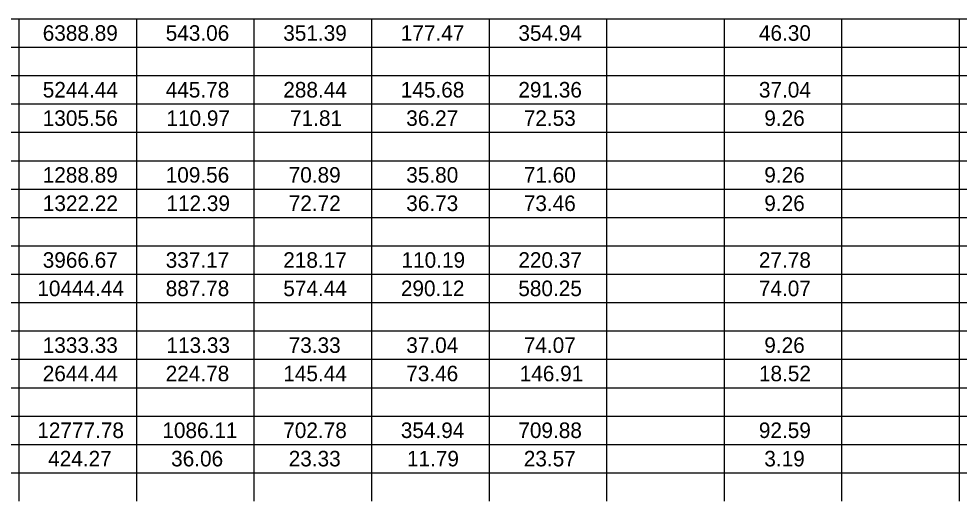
# Model space of a CAD drawing. Extents: x 0 to 34.4, y 0 to 47.
# Drawn here: x 16.38 to 25.65, y 5 to 9.75 of the extents above; entities that cross this region are included whole.
import ezdxf

# ---------------------------------------------------------------- set-up
doc = ezdxf.new("R2010")
doc.units = 0
doc.layers.add('SH_Text', color=7, linetype='Continuous')

msp = doc.modelspace()

# ---------------------------------------------------------------- linework, layer by layer
at = {"layer": 'SH_Text'}
for p, q in [((15.2196, 9.7518), (16.3784, 9.7518)), ((16.3784, 9.7518), (24.4903, 9.7518)), ((16.3784, 9.7518), (16.3784, 9.472)), ((17.5373, 9.7518), (17.5373, 9.472)), ((18.6961, 9.7518), (18.6961, 9.472)), ((19.855, 9.7518), (19.855, 9.472)), ((21.0138, 9.7518), (21.0138, 9.472)), ((22.1726, 9.7518), (22.1726, 9.472)), ((23.3315, 9.7518), (23.3315, 9.472)), ((24.4903, 9.7518), (25.6492, 9.7518)), ((24.4903, 9.7518), (24.4903, 9.472)), ((25.6492, 9.7518), (27.9668, 9.7518)), ((25.6492, 9.7518), (25.6492, 9.472)), ((15.2196, 9.472), (16.3784, 9.472)), ((16.3784, 9.472), (24.4903, 9.472)), ((16.3784, 9.472), (16.3784, 9.1923)), ((17.5373, 9.472), (17.5373, 9.1923)), ((18.6961, 9.472), (18.6961, 9.1923)), ((19.855, 9.472), (19.855, 9.1923)), ((21.0138, 9.472), (21.0138, 9.1923)), ((22.1726, 9.472), (22.1726, 9.1923)), ((23.3315, 9.472), (23.3315, 9.1923)), ((24.4903, 9.472), (25.6492, 9.472)), ((24.4903, 9.472), (24.4903, 9.1923)), ((25.6492, 9.472), (27.9668, 9.472)), ((25.6492, 9.472), (25.6492, 9.1923)), ((15.2196, 9.1923), (16.3784, 9.1923)), ((16.3784, 9.1923), (24.4903, 9.1923)), ((16.3784, 9.1923), (16.3784, 8.9126)), ((17.5373, 9.1923), (17.5373, 8.9126)), ((18.6961, 9.1923), (18.6961, 8.9126)), ((19.855, 9.1923), (19.855, 8.9126)), ((21.0138, 9.1923), (21.0138, 8.9126)), ((22.1726, 9.1923), (22.1726, 8.9126)), ((23.3315, 9.1923), (23.3315, 8.9126)), ((24.4903, 9.1923), (25.6492, 9.1923)), ((24.4903, 9.1923), (24.4903, 8.9126)), ((25.6492, 9.1923), (27.9668, 9.1923)), ((25.6492, 9.1923), (25.6492, 8.9126)), ((15.2196, 8.9126), (16.3784, 8.9126)), ((16.3784, 8.9126), (24.4903, 8.9126)), ((16.3784, 8.9126), (16.3784, 8.6329)), ((17.5373, 8.9126), (17.5373, 8.6329)), ((18.6961, 8.9126), (18.6961, 8.6329)), ((19.855, 8.9126), (19.855, 8.6329)), ((21.0138, 8.9126), (21.0138, 8.6329)), ((22.1726, 8.9126), (22.1726, 8.6329)), ((23.3315, 8.9126), (23.3315, 8.6329)), ((24.4903, 8.9126), (25.6492, 8.9126)), ((24.4903, 8.9126), (24.4903, 8.6329)), ((25.6492, 8.9126), (27.9668, 8.9126)), ((25.6492, 8.9126), (25.6492, 8.6329)), ((15.2196, 8.6329), (16.3784, 8.6329)), ((16.3784, 8.6329), (24.4903, 8.6329)), ((16.3784, 8.6329), (16.3784, 8.3532)), ((17.5373, 8.6329), (17.5373, 8.3532)), ((18.6961, 8.6329), (18.6961, 8.3532)), ((19.855, 8.6329), (19.855, 8.3532)), ((21.0138, 8.6329), (21.0138, 8.3532)), ((22.1726, 8.6329), (22.1726, 8.3532)), ((23.3315, 8.6329), (23.3315, 8.3532)), ((24.4903, 8.6329), (25.6492, 8.6329)), ((24.4903, 8.6329), (24.4903, 8.3532)), ((25.6492, 8.6329), (27.9668, 8.6329)), ((25.6492, 8.6329), (25.6492, 8.3532)), ((15.2196, 8.3532), (16.3784, 8.3532)), ((16.3784, 8.3532), (24.4903, 8.3532)), ((16.3784, 8.3532), (16.3784, 8.0734)), ((17.5373, 8.3532), (17.5373, 8.0734)), ((18.6961, 8.3532), (18.6961, 8.0734)), ((19.855, 8.3532), (19.855, 8.0734)), ((21.0138, 8.3532), (21.0138, 8.0734)), ((22.1726, 8.3532), (22.1726, 8.0734)), ((23.3315, 8.3532), (23.3315, 8.0734)), ((24.4903, 8.3532), (25.6492, 8.3532)), ((24.4903, 8.3532), (24.4903, 8.0734)), ((25.6492, 8.3532), (27.9668, 8.3532)), ((25.6492, 8.3532), (25.6492, 8.0734)), ((15.2196, 8.0734), (16.3784, 8.0734)), ((16.3784, 8.0734), (24.4903, 8.0734)), ((16.3784, 8.0734), (16.3784, 7.7937)), ((17.5373, 8.0734), (17.5373, 7.7937)), ((18.6961, 8.0734), (18.6961, 7.7937)), ((19.855, 8.0734), (19.855, 7.7937)), ((21.0138, 8.0734), (21.0138, 7.7937)), ((22.1726, 8.0734), (22.1726, 7.7937)), ((23.3315, 8.0734), (23.3315, 7.7937)), ((24.4903, 8.0734), (25.6492, 8.0734)), ((24.4903, 8.0734), (24.4903, 7.7937)), ((25.6492, 8.0734), (27.9668, 8.0734)), ((25.6492, 8.0734), (25.6492, 7.7937)), ((15.2196, 7.7937), (16.3784, 7.7937)), ((16.3784, 7.7937), (24.4903, 7.7937)), ((16.3784, 7.7937), (16.3784, 7.514)), ((17.5373, 7.7937), (17.5373, 7.514)), ((18.6961, 7.7937), (18.6961, 7.514)), ((19.855, 7.7937), (19.855, 7.514)), ((21.0138, 7.7937), (21.0138, 7.514)), ((22.1726, 7.7937), (22.1726, 7.514)), ((23.3315, 7.7937), (23.3315, 7.514)), ((24.4903, 7.7937), (25.6492, 7.7937)), ((24.4903, 7.7937), (24.4903, 7.514)), ((25.6492, 7.7937), (27.9668, 7.7937)), ((25.6492, 7.7937), (25.6492, 7.514)), ((15.2196, 7.514), (16.3784, 7.514)), ((16.3784, 7.514), (24.4903, 7.514)), ((16.3784, 7.514), (16.3784, 7.2343)), ((17.5373, 7.514), (17.5373, 7.2343)), ((18.6961, 7.514), (18.6961, 7.2343)), ((19.855, 7.514), (19.855, 7.2343)), ((21.0138, 7.514), (21.0138, 7.2343)), ((22.1726, 7.514), (22.1726, 7.2343)), ((23.3315, 7.514), (23.3315, 7.2343)), ((24.4903, 7.514), (25.6492, 7.514)), ((24.4903, 7.514), (24.4903, 7.2343)), ((25.6492, 7.514), (27.9668, 7.514)), ((25.6492, 7.514), (25.6492, 7.2343)), ((15.2196, 7.2343), (16.3784, 7.2343)), ((16.3784, 7.2343), (24.4903, 7.2343)), ((16.3784, 7.2343), (16.3784, 6.9546)), ((17.5373, 7.2343), (17.5373, 6.9546)), ((18.6961, 7.2343), (18.6961, 6.9546)), ((19.855, 7.2343), (19.855, 6.9546)), ((21.0138, 7.2343), (21.0138, 6.9546)), ((22.1726, 7.2343), (22.1726, 6.9546)), ((23.3315, 7.2343), (23.3315, 6.9546)), ((24.4903, 7.2343), (25.6492, 7.2343)), ((24.4903, 7.2343), (24.4903, 6.9546)), ((25.6492, 7.2343), (27.9668, 7.2343)), ((25.6492, 7.2343), (25.6492, 6.9546)), ((15.2196, 6.9546), (16.3784, 6.9546)), ((16.3784, 6.9546), (24.4903, 6.9546)), ((16.3784, 6.9546), (16.3784, 6.6748)), ((17.5373, 6.9546), (17.5373, 6.6748)), ((18.6961, 6.9546), (18.6961, 6.6748)), ((19.855, 6.9546), (19.855, 6.6748)), ((21.0138, 6.9546), (21.0138, 6.6748)), ((22.1726, 6.9546), (22.1726, 6.6748)), ((23.3315, 6.9546), (23.3315, 6.6748)), ((24.4903, 6.9546), (25.6492, 6.9546)), ((24.4903, 6.9546), (24.4903, 6.6748)), ((25.6492, 6.9546), (27.9668, 6.9546)), ((25.6492, 6.9546), (25.6492, 6.6748)), ((15.2196, 6.6748), (16.3784, 6.6748)), ((16.3784, 6.6748), (24.4903, 6.6748)), ((16.3784, 6.6748), (16.3784, 6.3951)), ((17.5373, 6.6748), (17.5373, 6.3951)), ((18.6961, 6.6748), (18.6961, 6.3951)), ((19.855, 6.6748), (19.855, 6.3951)), ((21.0138, 6.6748), (21.0138, 6.3951)), ((22.1726, 6.6748), (22.1726, 6.3951)), ((23.3315, 6.6748), (23.3315, 6.3951)), ((24.4903, 6.6748), (25.6492, 6.6748)), ((24.4903, 6.6748), (24.4903, 6.3951)), ((25.6492, 6.6748), (27.9668, 6.6748)), ((25.6492, 6.6748), (25.6492, 6.3951)), ((15.2196, 6.3951), (16.3784, 6.3951)), ((16.3784, 6.3951), (24.4903, 6.3951)), ((16.3784, 6.3951), (16.3784, 6.1154)), ((17.5373, 6.3951), (17.5373, 6.1154)), ((18.6961, 6.3951), (18.6961, 6.1154)), ((19.855, 6.3951), (19.855, 6.1154)), ((21.0138, 6.3951), (21.0138, 6.1154)), ((22.1726, 6.3951), (22.1726, 6.1154)), ((23.3315, 6.3951), (23.3315, 6.1154)), ((24.4903, 6.3951), (25.6492, 6.3951)), ((24.4903, 6.3951), (24.4903, 6.1154)), ((25.6492, 6.3951), (27.9668, 6.3951)), ((25.6492, 6.3951), (25.6492, 6.1154)), ((15.2196, 6.1154), (16.3784, 6.1154)), ((16.3784, 6.1154), (24.4903, 6.1154)), ((16.3784, 6.1154), (16.3784, 5.8357)), ((17.5373, 6.1154), (17.5373, 5.8357)), ((18.6961, 6.1154), (18.6961, 5.8357)), ((19.855, 6.1154), (19.855, 5.8357)), ((21.0138, 6.1154), (21.0138, 5.8357)), ((22.1726, 6.1154), (22.1726, 5.8357)), ((23.3315, 6.1154), (23.3315, 5.8357)), ((24.4903, 6.1154), (25.6492, 6.1154)), ((24.4903, 6.1154), (24.4903, 5.8357)), ((25.6492, 6.1154), (27.9668, 6.1154)), ((25.6492, 6.1154), (25.6492, 5.8357)), ((15.2196, 5.8357), (16.3784, 5.8357)), ((16.3784, 5.8357), (24.4903, 5.8357)), ((16.3784, 5.8357), (16.3784, 5.556)), ((17.5373, 5.8357), (17.5373, 5.556)), ((18.6961, 5.8357), (18.6961, 5.556)), ((19.855, 5.8357), (19.855, 5.556)), ((21.0138, 5.8357), (21.0138, 5.556)), ((22.1726, 5.8357), (22.1726, 5.556)), ((23.3315, 5.8357), (23.3315, 5.556)), ((24.4903, 5.8357), (25.6492, 5.8357)), ((24.4903, 5.8357), (24.4903, 5.556)), ((25.6492, 5.8357), (27.9668, 5.8357)), ((25.6492, 5.8357), (25.6492, 5.556)), ((15.2196, 5.556), (16.3784, 5.556)), ((16.3784, 5.556), (24.4903, 5.556)), ((16.3784, 5.556), (16.3784, 4.9965)), ((17.5373, 5.556), (17.5373, 4.9965)), ((18.6961, 5.556), (18.6961, 4.9965)), ((19.855, 5.556), (19.855, 4.9965)), ((21.0138, 5.556), (21.0138, 4.9965)), ((22.1726, 5.556), (22.1726, 4.9965)), ((23.3315, 5.556), (23.3315, 4.9965)), ((24.4903, 5.556), (25.6492, 5.556)), ((24.4903, 5.556), (24.4903, 4.9965)), ((25.6492, 5.556), (27.9668, 5.556)), ((25.6492, 5.556), (25.6492, 4.9965)), ((15.2196, 5.2762), (16.3784, 5.2762)), ((16.3784, 5.2762), (24.4903, 5.2762)), ((24.4903, 5.2762), (25.6492, 5.2762)), ((25.6492, 5.2762), (27.9668, 5.2762))]:
    msp.add_line(p, q, dxfattribs=at)

# ---------------------------------------------------------------- texts
for s, p in [('6388.89', (16.6142, 9.5353)), ('543.06', (17.8266, 9.5353)), ('351.39', (18.9854, 9.5353)), ('177.47', (20.1443, 9.5353)), ('354.94', (21.3035, 9.5353)), ('46.30', (23.6746, 9.5353)), ('5244.44', (16.6146, 8.9759)), ('445.78', (17.8265, 8.9759)), ('288.44', (18.9858, 8.9759)), ('145.68', (20.1442, 8.9759)), ('291.36', (21.3032, 8.9759)), ('37.04', (23.6747, 8.9759)), ('1305.56', (16.6143, 8.6961)), ('110.97', (17.8338, 8.6961)), ('71.81', (19.0524, 8.6961)), ('36.27', (20.1978, 8.6961)), ('72.53', (21.3567, 8.6961)), ('9.26', (23.7279, 8.6961)), ('1288.89', (16.6142, 8.1367)), ('109.56', (17.8266, 8.1367)), ('70.89', (19.0389, 8.1367)), ('35.80', (20.1981, 8.1367)), ('71.60', (21.357, 8.1367)), ('9.26', (23.7279, 8.1367)), ('1322.22', (16.615, 7.857)), ('112.39', (17.8337, 7.857)), ('72.72', (19.0397, 7.857)), ('36.73', (20.1978, 7.857)), ('73.46', (21.3567, 7.857)), ('9.26', (23.7279, 7.857)), ('3966.67', (16.6143, 7.2976)), ('337.17', (17.8266, 7.2976)), ('218.17', (18.9855, 7.2976)), ('110.19', (20.1514, 7.2976)), ('220.37', (21.3032, 7.2976)), ('27.78', (23.6743, 7.2976)), ('10444.44', (16.561, 7.0178)), ('887.78', (17.8265, 7.0178)), ('574.44', (18.9858, 7.0178)), ('290.12', (20.145, 7.0178)), ('580.25', (21.3026, 7.0178)), ('74.07', (23.6744, 7.0178)), ('1333.33', (16.6143, 6.4584)), ('113.33', (17.8338, 6.4584)), ('73.33', (19.039, 6.4584)), ('37.04', (20.1982, 6.4584)), ('74.07', (21.3567, 6.4584)), ('9.26', (23.7279, 6.4584)), ('2644.44', (16.6146, 6.1787)), ('224.78', (17.8265, 6.1787)), ('145.44', (18.9858, 6.1787)), ('73.46', (20.1978, 6.1787)), ('146.91', (21.3165, 6.1787)), ('18.52', (23.6751, 6.1787)), ('12777.78', (16.5606, 5.6192)), ('1086.11', (17.7936, 5.6192)), ('702.78', (18.9854, 5.6192)), ('354.94', (20.1446, 5.6192)), ('709.88', (21.303, 5.6192)), ('92.59', (23.6743, 5.6192)), ('424.27', (16.6678, 5.3395)), ('36.06', (17.8802, 5.3395)), ('23.33', (19.039, 5.3395)), ('11.79', (20.2049, 5.3395)), ('23.57', (21.3567, 5.3395)), ('3.19', (23.7278, 5.3395))]:
    msp.add_text(s, height=0.15318, dxfattribs=at).set_placement(p)

doc.saveas('drawing.dxf')
